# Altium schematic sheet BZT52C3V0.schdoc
size 127 x 101 mm
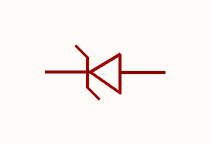
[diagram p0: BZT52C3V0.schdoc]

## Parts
D?  bzt52c3v0_c173414  [SOD-123_L2.7-W1.6-LS3.7-RD]  (value not drawn)

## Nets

Not connected (* = marked no-connect by the designer): D? 1(K) 2(A)

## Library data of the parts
D? = bzt52c3v0_c173414: 二极管配置:1个独立式;稳压值(标称值):3V;稳压值(范围值):2.85V~3.15V;耗散功率(Pd):500mW;; Manufacturer: MDD(辰达半导体); AddInBom: yes; ModelId: ad7e39f9e5534b3c96ffdc5532ebb493; ModelName: SOD-123_L2.7-W1.6-H1.4-LS3.7; ModelTransform: 146.026,62.992,0,180,0,0,0.0005,0,0; Diode Configuration: 1个独立式; Zener Voltage(Nom): 3V; Reverse Leakage Current (Ir): 50uA@1V; Pd - Power Dissipation: 500mW; Impedance(Zzt): 120Ω; Tolerance: ±5%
